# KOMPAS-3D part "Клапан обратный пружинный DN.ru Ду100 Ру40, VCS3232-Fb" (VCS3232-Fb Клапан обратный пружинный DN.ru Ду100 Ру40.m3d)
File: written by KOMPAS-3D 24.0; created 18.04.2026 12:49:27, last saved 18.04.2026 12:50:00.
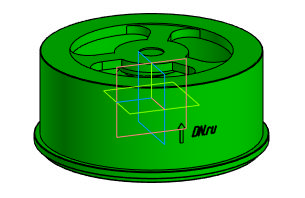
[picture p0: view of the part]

Document properties: Автор: 712; Полное имя файла: C:\Users\712\Desktop\Новая папка (4)\VCS3232-Fb Клапан обратный пружинный DN.ru Ду100 Ру40.m3d

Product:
- Component: Пружина 1086-1017 ГОСТ 18793-80  | qty 1  | additional columns: 3953604318-4147491677-0; Деталь; Пользователь Windows; c; Шероховатость не задана; Да; Сталь 10  ГОСТ 1050-88; source file: Деталь.m3d
- Body: Тело 1  | qty 1
    Масса: 3.671618
- Part/product: Клапан обратный пружинный DN.ru Ду100 Ру40  | designation VCS3232-Fb
    Масса: 3
    Раздел спецификации: Прочие изделия
    Примечание: D100-03898
    additional columns: 071bd168-1a06-425c-849c-e99e84a96128; Деталь; 712; c; Шероховатость не задана; Да

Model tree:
1. Операция без истории:2

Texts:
  VCS3232-Fb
